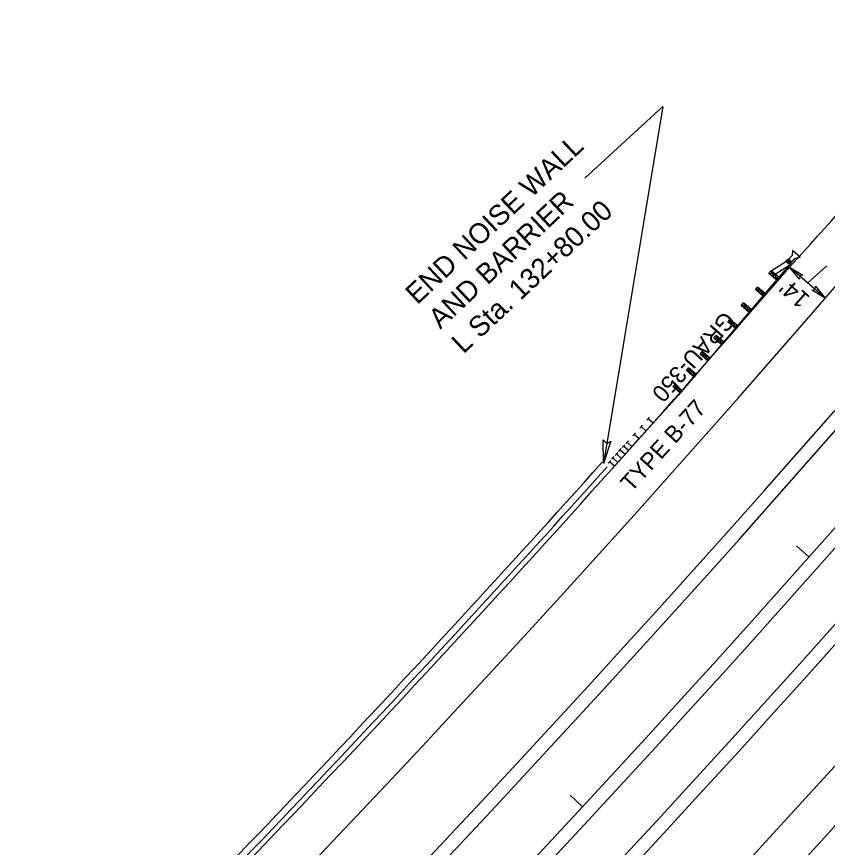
# Model space of a CAD drawing. Extents: x 2389694 to 2405615, y 547005 to 573532.
# Drawn here: x 2399006 to 2399246.4, y 560735.8 to 560982.2 of the extents above; entities that cross this region are included whole.
import ezdxf

# ---------------------------------------------------------------- set-up
doc = ezdxf.new("R2010")
doc.units = 0
for name, color, linetype in [('Old_Level_11', 7, 'Continuous'), ('Prop Cable Guiderail Double Face', 7, 'Continuous'), ('Prop Conc Barrier Precast Reinforced Single Face', 7, 'Continuous'), ('Prop Dimension', 7, 'Continuous'), ('Prop Dimension Text', 7, 'Continuous'), ('Prop DSN Text', 7, 'Continuous'), ('Prop EOT', 7, 'Continuous'), ('Prop GRAU 350 Approach CELL', 7, 'Continuous'), ('Prop Guardrail', 7, 'Continuous'), ('Prop Horizontal Alignment', 7, 'Continuous'), ('Prop Horizontal Alignment Tick Small', 7, 'Continuous'), ('Prop Noise Wall', 7, 'Continuous'), ('Prop SAU III Approach CELL', 7, 'Continuous')]:
    doc.layers.add(name, color=color, linetype=linetype)

# ---------------------------------------------------------------- blocks, each defined once
blk = doc.blocks.new('TERM')
at = {"layer": 'Old_Level_11'}
blk.add_lwpolyline([(-0.01375, 0.00225), (0, 0), (-0.01375, -0.0025), (-0.012, 0)], close=True, dxfattribs=at)

msp = doc.modelspace()

# ---------------------------------------------------------------- linework, layer by layer
at = {"layer": 'Prop Cable Guiderail Double Face'}
msp.add_arc((2395689.31, 563976), 4754, 315.06056, 2.8963, dxfattribs=at)
at = {"layer": 'Prop Conc Barrier Precast Reinforced Single Face'}
msp.add_arc((2395689.31, 563976), 4687.5, 315.06056, 318.15116, dxfattribs=at)
at = {"layer": 'Prop Dimension'}
for p, q in [((2399174.46, 560934.26), (2399197.54, 560955.54)), ((2399197.54, 560955.54), (2399179.95, 560849.66)), ((2399245.73, 560898.65), (2399235.17, 560907.85)), ((2399246.25, 560908.28), (2399240.54, 560903.18))]:
    msp.add_line(p, q, dxfattribs=at)
for points in [[(2399238.06, 560904.31), (2399235.17, 560907.85), (2399239.11, 560905.48), (2399238.15, 560905.26)], [(2399242.85, 560902.2), (2399245.73, 560898.65), (2399241.79, 560901.02), (2399242.75, 560901.25)]]:
    msp.add_lwpolyline(points, close=True, dxfattribs=at)
at = {"layer": 'Prop EOT'}
for centre, radius, start, end in [((2395689.31, 563976), 4769, 315.06056, 2.8963), ((2395689.31, 563976), 4773, 315.06056, 2.8963), ((2395689.31, 563976), 4797, 315.06056, 2.8963), ((2395689.31, 563976), 4727, 315.06056, 2.8963), ((2395689.31, 563976), 4731, 315.06056, 2.8963), ((2395689.31, 563976), 4703, 315.06056, 2.8963), ((2395689.31, 563976), 4809, 315.06056, 322.06524), ((2395629.6, 564155.36), 4852.47, 317.99092, 319.157), ((2395689.31, 563976), 4689, 315.06056, 319.13122)]:
    msp.add_arc(centre, radius, start, end, dxfattribs=at)
at = {"layer": 'Prop GRAU 350 Approach CELL'}
for p, q in [((2399236.07, 560912.79), (2399235.93, 560911.34)), ((2399238.27, 560910.85), (2399236.07, 560912.79)), ((2399229.69, 560906.8), (2399234.06, 560909.52)), ((2399234.06, 560909.52), (2399234.71, 560910.28)), ((2399234.06, 560909.52), (2399234.38, 560909.9)), ((2399235.2, 560908.55), (2399234.06, 560909.52)), ((2399235.85, 560909.31), (2399234.06, 560909.52)), ((2399235.93, 560911.34), (2399234.57, 560909.81)), ((2399234.57, 560909.81), (2399235.03, 560909.41)), ((2399235.85, 560909.31), (2399234.71, 560910.28)), ((2399234.71, 560910.28), (2399235.2, 560908.55)), ((2399235.03, 560909.41), (2399235.49, 560909)), ((2399235.49, 560909), (2399236.84, 560910.54)), ((2399236.84, 560910.54), (2399238.27, 560910.85)), ((2399203.11, 560870.85), (2399235.53, 560908.93)), ((2399230.86, 560905.81), (2399235.2, 560908.55)), ((2399229.04, 560906.04), (2399229.69, 560906.8)), ((2399231.38, 560904.05), (2399229.04, 560906.04)), ((2399230.86, 560905.81), (2399229.04, 560906.04)), ((2399232.02, 560904.82), (2399229.69, 560906.8)), ((2399229.69, 560906.8), (2399230.21, 560905.05)), ((2399230.21, 560905.05), (2399230.86, 560905.81)), ((2399230.21, 560905.05), (2399232.02, 560904.82)), ((2399231.38, 560904.05), (2399230.86, 560905.81)), ((2399225.01, 560901.2), (2399225.66, 560901.96)), ((2399227.94, 560900.02), (2399225.66, 560901.96)), ((2399225.66, 560901.96), (2399226.15, 560900.23)), ((2399227.29, 560899.26), (2399225.01, 560901.2)), ((2399226.8, 560900.99), (2399225.01, 560901.2)), ((2399226.15, 560900.23), (2399226.8, 560900.99)), ((2399226.15, 560900.23), (2399227.94, 560900.02)), ((2399227.29, 560899.26), (2399226.8, 560900.99)), ((2399220.82, 560896.49), (2399221.47, 560897.25)), ((2399223.85, 560895.22), (2399221.47, 560897.25)), ((2399221.47, 560897.25), (2399222.01, 560895.47)), ((2399223.21, 560894.46), (2399220.82, 560896.49)), ((2399222.66, 560896.24), (2399220.82, 560896.49)), ((2399222.01, 560895.47), (2399222.66, 560896.24)), ((2399222.01, 560895.47), (2399223.85, 560895.22)), ((2399223.21, 560894.46), (2399222.66, 560896.24)), ((2399216.81, 560891.63), (2399217.46, 560892.39)), ((2399219.77, 560890.42), (2399217.46, 560892.39)), ((2399217.46, 560892.39), (2399217.97, 560890.64)), ((2399219.12, 560889.66), (2399216.81, 560891.63)), ((2399218.61, 560891.41), (2399216.81, 560891.63)), ((2399217.97, 560890.64), (2399218.61, 560891.41)), ((2399217.97, 560890.64), (2399219.77, 560890.42)), ((2399219.12, 560889.66), (2399218.61, 560891.41)), ((2399219.12, 560889.66), (2399219.77, 560890.42)), ((2399212.72, 560886.84), (2399213.36, 560887.6)), ((2399215.69, 560885.62), (2399213.36, 560887.6)), ((2399213.36, 560887.6), (2399213.88, 560885.85)), ((2399215.04, 560884.86), (2399212.72, 560886.84)), ((2399214.52, 560886.61), (2399212.72, 560886.84)), ((2399213.88, 560885.85), (2399214.52, 560886.61)), ((2399213.88, 560885.85), (2399215.69, 560885.62)), ((2399215.04, 560884.86), (2399214.52, 560886.61)), ((2399208.63, 560882.04), (2399209.28, 560882.81)), ((2399211.6, 560880.83), (2399209.28, 560882.81)), ((2399209.28, 560882.81), (2399209.79, 560881.05)), ((2399210.95, 560880.06), (2399208.63, 560882.04)), ((2399210.44, 560881.82), (2399208.63, 560882.04)), ((2399209.79, 560881.05), (2399210.44, 560881.82)), ((2399209.79, 560881.05), (2399211.6, 560880.83)), ((2399210.95, 560880.06), (2399210.44, 560881.82)), ((2399204.58, 560877.21), (2399205.23, 560877.97)), ((2399207.52, 560876.03), (2399205.23, 560877.97)), ((2399205.23, 560877.97), (2399205.72, 560876.24)), ((2399206.87, 560875.27), (2399204.58, 560877.21)), ((2399206.37, 560877), (2399204.58, 560877.21)), ((2399205.72, 560876.24), (2399206.37, 560877)), ((2399205.72, 560876.24), (2399207.52, 560876.03)), ((2399207.52, 560876.03), (2399206.37, 560877)), ((2399206.37, 560877), (2399206.87, 560875.27)), ((2399206.87, 560875.27), (2399207.52, 560876.03)), ((2399201.19, 560873.21), (2399200.53, 560872.47)), ((2399202.77, 560870.48), (2399200.53, 560872.47)), ((2399200.53, 560872.47), (2399202.32, 560872.22)), ((2399203.44, 560871.22), (2399201.19, 560873.21)), ((2399201.65, 560871.47), (2399201.19, 560873.21)), ((2399201.65, 560871.47), (2399202.32, 560872.22)), ((2399203.44, 560871.22), (2399201.65, 560871.47)), ((2399202.32, 560872.22), (2399202.77, 560870.48)), ((2399202.77, 560870.48), (2399203.44, 560871.22))]:
    msp.add_line(p, q, dxfattribs=at)
at = {"layer": 'Prop Guardrail'}
msp.add_line((2399203.11, 560870.85), (2399194.74, 560861.56), dxfattribs=at)
at = {"layer": 'Prop Horizontal Alignment'}
msp.add_arc((2395689.31, 563976), 4750, 315.06056, 2.8963, dxfattribs=at)
at = {"layer": 'Prop Horizontal Alignment Tick Small'}
for p, q in [((2399240.93, 560821.88), (2399237.19, 560825.2)), ((2399173.74, 560747.82), (2399170.08, 560751.21))]:
    msp.add_line(p, q, dxfattribs=at)
at = {"layer": 'Prop Noise Wall'}
msp.add_arc((2395689.31, 563976), 4685.5, 315.06056, 318.15116, dxfattribs=at)
at = {"layer": 'Prop SAU III Approach CELL'}
for p, q in [((2399192.87, 560862.48), (2399193.64, 560863.33)), ((2399194.74, 560861.56), (2399193.26, 560862.9)), ((2399182.17, 560847.65), (2399194.74, 560861.56)), ((2399190.78, 560860.16), (2399191.55, 560861.01)), ((2399192.65, 560859.24), (2399191.16, 560860.58)), ((2399188.68, 560857.84), (2399189.45, 560858.69)), ((2399190.55, 560856.92), (2399189.07, 560858.26)), ((2399185.54, 560854.36), (2399186.31, 560855.21)), ((2399186.59, 560855.52), (2399187.36, 560856.37)), ((2399188.46, 560854.6), (2399186.97, 560855.94)), ((2399183.45, 560852.04), (2399184.21, 560852.89)), ((2399184.49, 560853.2), (2399185.26, 560854.05)), ((2399186.36, 560852.29), (2399184.88, 560853.63)), ((2399187.41, 560853.44), (2399185.93, 560854.79)), ((2399181.35, 560849.72), (2399182.12, 560850.57)), ((2399182.4, 560850.88), (2399183.17, 560851.73)), ((2399184.27, 560849.97), (2399182.78, 560851.31)), ((2399185.31, 560851.13), (2399183.83, 560852.47)), ((2399183.22, 560848.81), (2399181.74, 560850.15))]:
    msp.add_line(p, q, dxfattribs=at)

# ---------------------------------------------------------------- block references
at = {"layer": 'Prop Guardrail', "xscale": 500, "yscale": 500, "rotation": -99.43261961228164}
msp.add_blockref('TERM', (2399179.95, 560849.66), dxfattribs=at)

# ---------------------------------------------------------------- texts
at = {"layer": 'Prop Dimension Text'}
for s, height, rotation, p in [('END NOISE WALL ', 6, 43.1508, (2399124.75, 560896.55)), ('AND BARRIER', 6, 43.1508, (2399131.59, 560889.26)), ('L Sta. 132+80.00', 6, 43.1508, (2399138.43, 560881.96)), ("14'", 5, 138.4754, (2399241.49, 560899)), ('TYPE B-77', 5, 47.8782, (2399188.28, 560840.91))]:
    msp.add_text(s, height=height, rotation=rotation, dxfattribs=at).set_placement(p)
at = {"layer": 'Prop DSN Text'}
msp.add_text('GRAU-350', height=5, rotation=228.3181, dxfattribs=at).set_placement((2399215.73, 560895.11))

doc.saveas('drawing.dxf')
